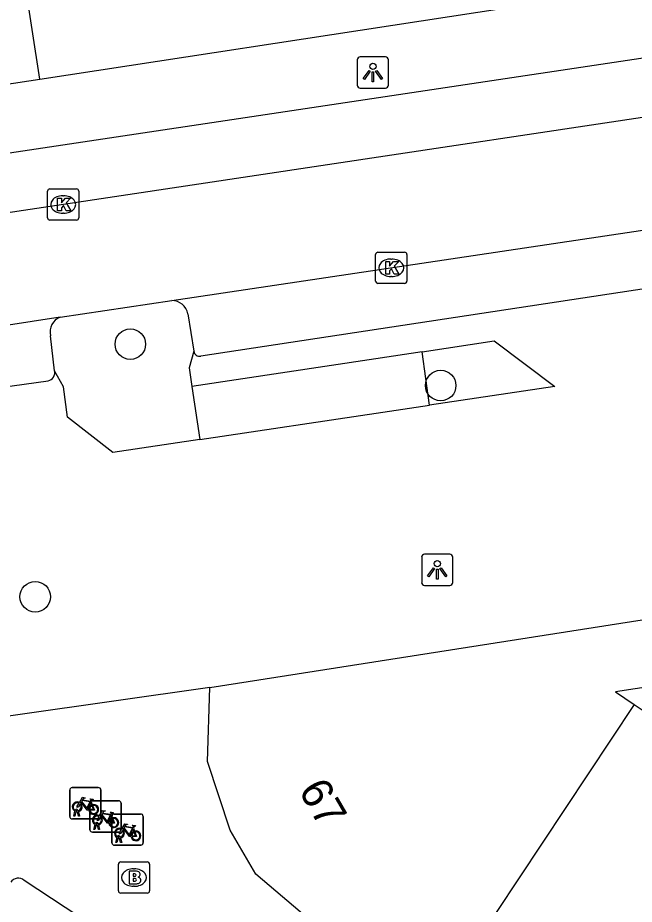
# Model space of a CAD drawing. Extents: x 159280 to 160375, y 384531 to 385872.
# Drawn here: x 159959.91 to 159979.67, y 384916.91 to 384945.31 of the extents above; entities that cross this region are included whole.
import ezdxf

# ---------------------------------------------------------------- set-up
doc = ezdxf.new("R2010")
doc.units = 0
for name, color, linetype in [('IMGEO_Boom', 7, 'Continuous'), ('IMGEO_Brandkraan', 7, 'Continuous'), ('IMGEO_Fietsenrek', 7, 'Continuous'), ('IMGEO_Haag', 7, 'Continuous'), ('IMGEO_Kolk', 7, 'Continuous'), ('IMGEO_Lichtpunt', 7, 'Continuous'), ('IMGEO_Pand', 7, 'Continuous'), ('IMGEO_Pand_nummerreeks', 7, 'Continuous'), ('IMGEO_Parkeervlak_open', 7, 'Continuous'), ('IMGEO_Rijbaan_lokaal_open', 7, 'Continuous'), ('IMGEO_Voetpad_open', 7, 'Continuous')]:
    doc.layers.add(name, color=color, linetype=linetype)

msp = doc.modelspace()

# ---------------------------------------------------------------- linework, layer by layer
at = {"layer": 'IMGEO_Boom'}
for centre in [(159963.522, 384934.849), (159973.467, 384933.524), (159960.474, 384926.758)]:
    msp.add_circle(centre, 0.489, dxfattribs=at)
at = {"layer": 'IMGEO_Brandkraan'}
for p, q in [((159963.213, 384918.262), (159964.065, 384918.262)), ((159963.138, 384917.336), (159963.138, 384918.188)), ((159963.626, 384918.042), (159963.651, 384918.042)), ((159964.139, 384918.188), (159964.139, 384917.336)), ((159963.649, 384917.482), (159963.624, 384917.482)), ((159964.065, 384917.262), (159963.213, 384917.262))]:
    msp.add_line(p, q, dxfattribs=at)
for points in [[(159963.213, 384918.262), (159964.065, 384918.262)], [(159963.138, 384917.336), (159963.138, 384918.188)], [(159964.139, 384918.188), (159964.139, 384917.336)], [(159963.486, 384917.962), (159963.486, 384917.562), (159963.699, 384917.562)], [(159963.717, 384917.962), (159963.486, 384917.962)], [(159963.665, 384917.881), (159963.611, 384917.881), (159963.611, 384917.805)], [(159963.611, 384917.805), (159963.664, 384917.805)], [(159963.673, 384917.729), (159963.611, 384917.729), (159963.611, 384917.648)], [(159963.611, 384917.648), (159963.673, 384917.648)], [(159964.065, 384917.262), (159963.213, 384917.262)]]:
    msp.add_lwpolyline(points, dxfattribs=at)
for centre, radius, start, end in [((159963.215, 384918.186), 0.0765, 91.552, 178.448), ((159963.215, 384918.186), 0.0765, 91.552, 178.448), ((159964.063, 384918.186), 0.0765, 1.552, 88.448), ((159964.063, 384918.186), 0.0765, 1.552, 88.448), ((159963.666, 384917.843), 0.0379, 267.8285, 90.9355), ((159963.674, 384917.688), 0.0404, 269.8759, 90.5077), ((159963.721, 384917.817), 0.145, 59.4692, 91.5367), ((159963.746, 384917.864), 0.0922, 285.5137, 58.1501), ((159963.751, 384917.672), 0.105, 301.3115, 78.989), ((159963.705, 384917.813), 0.251, 268.6676, 293.5347), ((159963.215, 384917.338), 0.0765, 181.552, 268.448), ((159963.215, 384917.338), 0.0765, 181.552, 268.448), ((159964.063, 384917.338), 0.0765, 271.552, 358.448), ((159964.063, 384917.338), 0.0765, 271.552, 358.448)]:
    msp.add_arc(centre, radius, start, end, dxfattribs=at)
for centre, major_axis, ratio, start_param, end_param in [((159963.625, 384917.762), (-0.387, 0.002), 0.722429, 4.712389, 7.853982), ((159963.65, 384917.762), (-0.39, 0.002), 0.717154, 1.570796, 4.712389)]:
    msp.add_ellipse(centre, major_axis=major_axis, ratio=ratio, start_param=start_param, end_param=end_param, dxfattribs=at)
at = {"layer": 'IMGEO_Fietsenrek'}
for p, q in [((159961.58, 384919.718), (159961.58, 384920.559)), ((159961.58, 384920.559), (159961.58, 384919.718)), ((159961.655, 384920.643), (159962.496, 384920.643)), ((159962.496, 384920.643), (159961.655, 384920.643)), ((159962.58, 384920.568), (159962.58, 384919.727)), ((159962.58, 384919.727), (159962.58, 384920.568)), ((159962.226, 384919.294), (159962.226, 384920.135)), ((159962.226, 384920.135), (159962.226, 384919.294)), ((159962.267, 384920.192), (159962.303, 384920.097)), ((159962.301, 384920.219), (159963.142, 384920.219)), ((159963.142, 384920.219), (159962.301, 384920.219)), ((159963.226, 384920.144), (159963.226, 384919.303)), ((159963.226, 384919.303), (159963.226, 384920.144)), ((159961.707, 384919.727), (159961.746, 384919.887)), ((159961.741, 384919.727), (159961.707, 384919.727)), ((159961.776, 384919.875), (159961.741, 384919.727)), ((159961.818, 384919.899), (159961.817, 384919.903)), ((159961.859, 384919.727), (159961.825, 384919.869)), ((159961.849, 384919.91), (159961.85, 384919.903)), ((159961.857, 384919.873), (159961.892, 384919.727)), ((159961.892, 384919.727), (159961.859, 384919.727)), ((159962.913, 384919.768), (159962.949, 384919.673)), ((159962.933, 384918.873), (159962.933, 384919.714)), ((159962.933, 384919.714), (159962.933, 384918.873)), ((159963.008, 384919.798), (159963.849, 384919.798)), ((159963.849, 384919.798), (159963.008, 384919.798)), ((159963.933, 384919.723), (159963.933, 384918.882)), ((159963.933, 384918.882), (159963.933, 384919.723)), ((159962.505, 384919.643), (159961.664, 384919.643)), ((159961.664, 384919.643), (159962.505, 384919.643)), ((159962.353, 384919.303), (159962.392, 384919.463)), ((159962.422, 384919.451), (159962.387, 384919.303)), ((159962.464, 384919.475), (159962.463, 384919.479)), ((159962.505, 384919.303), (159962.471, 384919.445)), ((159962.495, 384919.486), (159962.496, 384919.479)), ((159962.503, 384919.449), (159962.538, 384919.303)), ((159963.151, 384919.219), (159962.31, 384919.219)), ((159962.31, 384919.219), (159963.151, 384919.219)), ((159962.387, 384919.303), (159962.353, 384919.303)), ((159962.538, 384919.303), (159962.505, 384919.303)), ((159963.62, 384919.347), (159963.656, 384919.252)), ((159963.06, 384918.882), (159963.099, 384919.042)), ((159963.094, 384918.882), (159963.06, 384918.882)), ((159963.129, 384919.03), (159963.094, 384918.882)), ((159963.171, 384919.054), (159963.17, 384919.058)), ((159963.212, 384918.882), (159963.178, 384919.024)), ((159963.202, 384919.065), (159963.203, 384919.058)), ((159963.21, 384919.028), (159963.245, 384918.882)), ((159963.245, 384918.882), (159963.212, 384918.882)), ((159963.858, 384918.798), (159963.017, 384918.798)), ((159963.017, 384918.798), (159963.858, 384918.798))]:
    msp.add_line(p, q, dxfattribs=at)
for points in [[(159961.893, 384920.169), (159961.988, 384920.333), (159962.074, 384920.319), (159962.076, 384920.31), (159962.02, 384920.299), (159961.993, 384920.254), (159962.249, 384920.213)], [(159962.249, 384920.213), (159962.274, 384920.262), (159962.268, 384920.266), (159962.245, 384920.27), (159962.233, 384920.277), (159962.232, 384920.28), (159962.234, 384920.285), (159962.329, 384920.27), (159962.331, 384920.26), (159962.321, 384920.247), (159962.309, 384920.241), (159962.295, 384920.247), (159962.267, 384920.192)], [(159961.914, 384920.117), (159961.862, 384920.027), (159961.822, 384920.002), (159961.823, 384920.049), (159961.878, 384920.143)], [(159962.189, 384919.925), (159962.139, 384919.925), (159961.948, 384920.176), (159961.929, 384920.144)], [(159962.236, 384920.188), (159961.979, 384920.229), (159961.962, 384920.2), (159962.129, 384919.98), (159962.236, 384920.188)], [(159962.284, 384920.09), (159962.254, 384920.167), (159962.145, 384919.949), (159962.188, 384919.949)], [(159962.218, 384919.949), (159962.338, 384919.948), (159962.294, 384920.062)], [(159962.314, 384920.069), (159962.369, 384919.924), (159962.219, 384919.924)], [(159962.56, 384919.693), (159962.508, 384919.603), (159962.468, 384919.578), (159962.469, 384919.625), (159962.524, 384919.719)], [(159962.539, 384919.745), (159962.634, 384919.909), (159962.72, 384919.895), (159962.722, 384919.886), (159962.666, 384919.875), (159962.639, 384919.83), (159962.895, 384919.789)], [(159962.835, 384919.501), (159962.785, 384919.501), (159962.594, 384919.752), (159962.575, 384919.72)], [(159962.882, 384919.764), (159962.625, 384919.805), (159962.608, 384919.776), (159962.775, 384919.556), (159962.882, 384919.764)], [(159962.93, 384919.666), (159962.9, 384919.743), (159962.791, 384919.525), (159962.834, 384919.525)], [(159962.895, 384919.789), (159962.92, 384919.838), (159962.914, 384919.842), (159962.891, 384919.846), (159962.879, 384919.853), (159962.878, 384919.856), (159962.88, 384919.861), (159962.975, 384919.846), (159962.977, 384919.836), (159962.967, 384919.823), (159962.955, 384919.817), (159962.941, 384919.823), (159962.913, 384919.768)], [(159962.864, 384919.525), (159962.984, 384919.524), (159962.94, 384919.638)], [(159962.96, 384919.645), (159963.015, 384919.5), (159962.865, 384919.5)], [(159963.246, 384919.324), (159963.341, 384919.488), (159963.427, 384919.474), (159963.429, 384919.465), (159963.373, 384919.454), (159963.346, 384919.409), (159963.602, 384919.368)], [(159963.589, 384919.343), (159963.332, 384919.384), (159963.315, 384919.355), (159963.482, 384919.135), (159963.589, 384919.343)], [(159963.602, 384919.368), (159963.627, 384919.417), (159963.621, 384919.421), (159963.598, 384919.425), (159963.586, 384919.432), (159963.585, 384919.435), (159963.587, 384919.44), (159963.682, 384919.425), (159963.684, 384919.415), (159963.674, 384919.402), (159963.662, 384919.396), (159963.648, 384919.402), (159963.62, 384919.347)], [(159963.267, 384919.272), (159963.215, 384919.182), (159963.175, 384919.157), (159963.176, 384919.204), (159963.231, 384919.298)], [(159963.542, 384919.08), (159963.492, 384919.08), (159963.301, 384919.331), (159963.282, 384919.299)], [(159963.637, 384919.245), (159963.607, 384919.322), (159963.498, 384919.104), (159963.541, 384919.104)], [(159963.571, 384919.104), (159963.691, 384919.103), (159963.647, 384919.217)], [(159963.667, 384919.224), (159963.722, 384919.079), (159963.572, 384919.079)]]:
    msp.add_lwpolyline(points, dxfattribs=at)
for centre, radius, start, end in [((159961.658, 384920.565), 0.0779, 92.4484, 184.2845), ((159961.658, 384920.565), 0.0779, 92.4484, 184.2845), ((159962.502, 384920.565), 0.0779, 2.4484, 94.2845), ((159962.502, 384920.565), 0.0779, 2.4484, 94.2845), ((159961.82, 384920.028), 0.159, 62.6766, 242.1369), ((159961.82, 384920.028), 0.129, 63.3192, 238.903), ((159961.82, 384920.028), 0.129, 283.6043, 43.4302), ((159961.82, 384920.028), 0.159, 283.5766, 46.6042), ((159962.347, 384919.944), 0.159, 113.3408, 178.3217), ((159962.347, 384919.944), 0.159, 187.0065, 105.7708), ((159962.347, 384919.944), 0.129, 113.923, 177.9556), ((159962.347, 384919.944), 0.129, 188.6715, 104.5883), ((159962.304, 384920.141), 0.0779, 92.4484, 184.2845), ((159962.304, 384920.141), 0.0779, 92.4484, 184.2845), ((159963.148, 384920.141), 0.0779, 2.4484, 94.2845), ((159963.148, 384920.141), 0.0779, 2.4484, 94.2845), ((159961.658, 384919.721), 0.0779, 182.4484, 274.2845), ((159961.658, 384919.721), 0.0779, 182.4484, 274.2845), ((159961.8, 384919.899), 0.0499, 12.8025, 158.6934), ((159961.82, 384920.028), 0.159, 253.9967, 271.7867), ((159961.8, 384919.899), 0.0174, 12.8025, 163.4502), ((159961.82, 384920.028), 0.129, 253.415, 269.0204), ((159962.466, 384919.604), 0.159, 62.6766, 242.1369), ((159962.466, 384919.604), 0.129, 63.3192, 238.903), ((159962.466, 384919.604), 0.129, 283.6043, 43.4302), ((159962.466, 384919.604), 0.159, 283.5766, 46.6042), ((159962.502, 384919.721), 0.0779, 272.4484, 4.2845), ((159962.502, 384919.721), 0.0779, 272.4484, 4.2845), ((159962.993, 384919.52), 0.159, 187.0065, 105.7708), ((159963.011, 384919.72), 0.0779, 92.4484, 184.2845), ((159963.011, 384919.72), 0.0779, 92.4484, 184.2845), ((159963.855, 384919.72), 0.0779, 2.4484, 94.2845), ((159963.855, 384919.72), 0.0779, 2.4484, 94.2845), ((159962.446, 384919.475), 0.0499, 12.8025, 158.6934), ((159962.466, 384919.604), 0.159, 253.9967, 271.7867), ((159962.446, 384919.475), 0.0174, 12.8025, 163.4502), ((159962.466, 384919.604), 0.129, 253.415, 269.0204), ((159962.993, 384919.52), 0.159, 113.3408, 178.3217), ((159962.993, 384919.52), 0.129, 113.923, 177.9556), ((159962.993, 384919.52), 0.129, 188.6715, 104.5883), ((159962.304, 384919.297), 0.0779, 182.4484, 274.2845), ((159962.304, 384919.297), 0.0779, 182.4484, 274.2845), ((159963.173, 384919.183), 0.159, 62.6766, 242.1369), ((159963.173, 384919.183), 0.129, 63.3192, 238.903), ((159963.153, 384919.054), 0.0499, 12.8025, 158.6934), ((159963.148, 384919.297), 0.0779, 272.4484, 4.2845), ((159963.148, 384919.297), 0.0779, 272.4484, 4.2845), ((159963.173, 384919.183), 0.129, 283.6043, 43.4302), ((159963.173, 384919.183), 0.159, 283.5766, 46.6042), ((159963.7, 384919.099), 0.159, 113.3408, 178.3217), ((159963.7, 384919.099), 0.159, 187.0065, 105.7708), ((159963.7, 384919.099), 0.129, 113.923, 177.9556), ((159963.7, 384919.099), 0.129, 188.6715, 104.5883), ((159963.011, 384918.876), 0.0779, 182.4484, 274.2845), ((159963.011, 384918.876), 0.0779, 182.4484, 274.2845), ((159963.173, 384919.183), 0.159, 253.9967, 271.7867), ((159963.153, 384919.054), 0.0174, 12.8025, 163.4502), ((159963.173, 384919.183), 0.129, 253.415, 269.0204), ((159963.855, 384918.876), 0.0779, 272.4484, 4.2845), ((159963.855, 384918.876), 0.0779, 272.4484, 4.2845)]:
    msp.add_arc(centre, radius, start, end, dxfattribs=at)
at = {"layer": 'IMGEO_Haag'}
for points in [[(159973.107, 384932.892), (159972.877, 384934.605)], [(159965.496, 384933.493), (159965.753, 384931.796)]]:
    msp.add_lwpolyline(points, dxfattribs=at)
at = {"layer": 'IMGEO_Kolk'}
for p, q in [((159960.87, 384938.898), (159960.87, 384939.75)), ((159960.945, 384939.824), (159961.797, 384939.824)), ((159961.358, 384939.604), (159961.383, 384939.604)), ((159961.871, 384939.75), (159961.871, 384938.898)), ((159961.381, 384939.044), (159961.356, 384939.044)), ((159961.797, 384938.824), (159960.945, 384938.824)), ((159971.383, 384936.871), (159971.383, 384937.723)), ((159971.458, 384937.797), (159972.31, 384937.797)), ((159971.871, 384937.577), (159971.896, 384937.577)), ((159972.384, 384937.723), (159972.384, 384936.871)), ((159971.894, 384937.017), (159971.869, 384937.017)), ((159972.31, 384936.797), (159971.458, 384936.797))]:
    msp.add_line(p, q, dxfattribs=at)
for points in [[(159960.87, 384938.898), (159960.87, 384939.75)], [(159960.945, 384939.824), (159961.797, 384939.824)], [(159961.871, 384939.75), (159961.871, 384938.898)], [(159961.191, 384939.524), (159961.314, 384939.524), (159961.314, 384939.373), (159961.444, 384939.524), (159961.608, 384939.524), (159961.462, 384939.373), (159961.615, 384939.124), (159961.463, 384939.124), (159961.378, 384939.288), (159961.314, 384939.221), (159961.314, 384939.124), (159961.191, 384939.124), (159961.191, 384939.524)], [(159961.797, 384938.824), (159960.945, 384938.824)], [(159971.383, 384936.871), (159971.383, 384937.723)], [(159971.458, 384937.797), (159972.31, 384937.797)], [(159972.384, 384937.723), (159972.384, 384936.871)], [(159971.704, 384937.497), (159971.827, 384937.497), (159971.827, 384937.346), (159971.957, 384937.497), (159972.121, 384937.497), (159971.975, 384937.346), (159972.128, 384937.097), (159971.976, 384937.097), (159971.891, 384937.261), (159971.827, 384937.194), (159971.827, 384937.097), (159971.704, 384937.097), (159971.704, 384937.497)], [(159972.31, 384936.797), (159971.458, 384936.797)]]:
    msp.add_lwpolyline(points, dxfattribs=at)
for centre, start, end in [((159960.947, 384939.748), 91.552, 178.448), ((159960.947, 384939.748), 91.552, 178.448), ((159961.795, 384939.748), 1.552, 88.448), ((159961.795, 384939.748), 1.552, 88.448), ((159960.947, 384938.9), 181.552, 268.448), ((159960.947, 384938.9), 181.552, 268.448), ((159961.795, 384938.9), 271.552, 358.448), ((159961.795, 384938.9), 271.552, 358.448), ((159971.46, 384937.721), 91.552, 178.448), ((159971.46, 384937.721), 91.552, 178.448), ((159972.308, 384937.721), 1.552, 88.448), ((159972.308, 384937.721), 1.552, 88.448), ((159971.46, 384936.873), 181.552, 268.448), ((159971.46, 384936.873), 181.552, 268.448), ((159972.308, 384936.873), 271.552, 358.448), ((159972.308, 384936.873), 271.552, 358.448)]:
    msp.add_arc(centre, 0.0765, start, end, dxfattribs=at)
for centre, major_axis, ratio, start_param, end_param in [((159961.357, 384939.324), (-0.387, 0.002), 0.722429, 4.712389, 7.853982), ((159961.382, 384939.324), (-0.39, 0.002), 0.717154, 1.570796, 4.712389), ((159971.87, 384937.297), (-0.387, 0.002), 0.722429, 4.712389, 7.853982), ((159971.895, 384937.297), (-0.39, 0.002), 0.717154, 1.570796, 4.712389)]:
    msp.add_ellipse(centre, major_axis=major_axis, ratio=ratio, start_param=start_param, end_param=end_param, dxfattribs=at)
at = {"layer": 'IMGEO_Lichtpunt'}
for p, q in [((159970.796, 384943.955), (159970.796, 384943.148)), ((159970.796, 384943.955), (159970.796, 384943.148)), ((159971.698, 384944.05), (159970.89, 384944.05)), ((159971.698, 384944.05), (159970.89, 384944.05)), ((159971.792, 384943.148), (159971.792, 384943.955)), ((159971.792, 384943.148), (159971.792, 384943.955)), ((159970.89, 384943.054), (159971.698, 384943.054)), ((159970.89, 384943.054), (159971.698, 384943.054)), ((159972.858, 384928.023), (159972.858, 384927.216)), ((159972.858, 384928.023), (159972.858, 384927.216)), ((159973.76, 384928.118), (159972.952, 384928.118)), ((159973.76, 384928.118), (159972.952, 384928.118)), ((159973.854, 384927.216), (159973.854, 384928.023)), ((159973.854, 384927.216), (159973.854, 384928.023)), ((159972.952, 384927.122), (159973.76, 384927.122)), ((159972.952, 384927.122), (159973.76, 384927.122))]:
    msp.add_line(p, q, dxfattribs=at)
for points in [[(159971.17, 384943.619), (159971.209, 384943.591), (159971.021, 384943.329), (159970.983, 384943.356), (159971.17, 384943.619)], [(159971.272, 384943.571), (159971.319, 384943.571), (159971.319, 384943.249), (159971.272, 384943.249), (159971.272, 384943.571)], [(159971.382, 384943.591), (159971.42, 384943.618), (159971.607, 384943.356), (159971.568, 384943.328), (159971.382, 384943.591)], [(159973.232, 384927.687), (159973.271, 384927.659), (159973.083, 384927.397), (159973.045, 384927.424), (159973.232, 384927.687)], [(159973.334, 384927.639), (159973.381, 384927.639), (159973.381, 384927.317), (159973.334, 384927.317), (159973.334, 384927.639)], [(159973.444, 384927.659), (159973.482, 384927.686), (159973.669, 384927.424), (159973.63, 384927.396), (159973.444, 384927.659)]]:
    msp.add_lwpolyline(points, dxfattribs=at)
for centre in [(159971.295, 384943.753), (159973.357, 384927.821)]:
    msp.add_circle(centre, 0.0994, dxfattribs=at)
for centre, start, end in [((159970.89, 384943.955), 90, 180), ((159970.89, 384943.955), 90, 180), ((159971.698, 384943.955), 0, 90), ((159971.698, 384943.955), 0, 90), ((159970.89, 384943.148), 180, 270), ((159970.89, 384943.148), 180, 270), ((159971.698, 384943.148), 270, 0), ((159971.698, 384943.148), 270, 360), ((159972.952, 384928.023), 90, 180), ((159972.952, 384928.023), 90, 180), ((159973.76, 384928.023), 0, 90), ((159973.76, 384928.023), 0, 90), ((159972.952, 384927.216), 180, 270), ((159972.952, 384927.216), 180, 270), ((159973.76, 384927.216), 270, 0), ((159973.76, 384927.216), 270, 360)]:
    msp.add_arc(centre, 0.0946, start, end, dxfattribs=at)
at = {"layer": 'IMGEO_Pand'}
for points in [[(159966.07, 384923.849), (159984.158, 384926.682)], [(159984.158, 384926.682), (159984.522, 384924.544), (159979.066, 384923.712), (159979.666, 384923.309)], [(159973.774, 384914.418), (159971.772, 384915.74), (159971.487, 384915.309), (159969.395, 384916.303), (159967.542, 384917.867), (159966.719, 384919.284), (159965.995, 384921.481), (159966.07, 384923.849)], [(159979.666, 384923.309), (159973.774, 384914.418)], [(159979.666, 384923.309), (159982.004, 384921.742), (159980.558, 384919.553), (159982.477, 384918.284)]]:
    msp.add_lwpolyline(points, dxfattribs=at)
at = {"layer": 'IMGEO_Parkeervlak_open'}
for points in [[(159965.368, 384935.821), (159965.558, 384934.629)], [(159961.091, 384934), (159960.966, 384935.121)]]:
    msp.add_lwpolyline(points, dxfattribs=at)
for centre, radius, start, end in [((159964.854, 384935.723), 0.523, 10.837, 90.6442), ((159961.474, 384935.238), 0.522, 112.8117, 192.9902)]:
    msp.add_arc(centre, radius, start, end, dxfattribs=at)
at = {"layer": 'IMGEO_Rijbaan_lokaal_open'}
for points in [[(159991.306, 384943.822), (159958.878, 384938.949)], [(159964.848, 384936.246), (159980.373, 384938.566)], [(159961.272, 384935.719), (159964.848, 384936.246)], [(159961.272, 384935.719), (159954.563, 384934.683)]]:
    msp.add_lwpolyline(points, dxfattribs=at)
at = {"layer": 'IMGEO_Voetpad_open'}
for points in [[(159959.209, 384940.91), (160040.921, 384953.179)], [(159960.619, 384943.336), (160000, 384949.373), (160022.714, 384952.82)], [(159960.619, 384943.336), (159960.15, 384946.398)], [(159958.571, 384943.024), (159960.619, 384943.336)], [(159980.232, 384936.834), (159980.06, 384936.63), (159965.782, 384934.464)], [(159972.877, 384934.605), (159975.185, 384934.952), (159977.123, 384933.49), (159973.107, 384932.892)], [(159965.558, 384934.629), (159965.406, 384934.087), (159965.496, 384933.493)], [(159972.877, 384934.605), (159971.384, 384934.38), (159965.496, 384933.493)], [(159965.753, 384931.796), (159962.964, 384931.38), (159961.505, 384932.507), (159961.378, 384933.479), (159961.091, 384934)], [(159955.425, 384932.916), (159960.891, 384933.677)], [(159965.753, 384931.796), (159971.614, 384932.669), (159973.107, 384932.892)], [(159966.07, 384923.849), (159950.751, 384921.669)], [(160017.484, 384877.679), (160017.389, 384877.749), (160017.267, 384877.853), (160017.156, 384877.969), (160017.055, 384878.093), (160016.965, 384878.227), (160016.888, 384878.367), (160016.823, 384878.515), (160016.772, 384878.667), (160016.735, 384878.823), (160016.712, 384878.982), (160016.628, 384879.955), (160016.593, 384880.076), (160016.548, 384880.193), (160016.493, 384880.306), (160016.427, 384880.414), (160016.353, 384880.515), (160016.269, 384880.609), (160016.232, 384880.646), (160000, 384891.362), (159975.638, 384907.458), (159970.364, 384910.928), (159967.975, 384912.5), (159960.117, 384917.67)]]:
    msp.add_lwpolyline(points, dxfattribs=at)
for centre, radius, start, end in [((159965.745, 384934.648), 0.187, 185.7169, 281.5318), ((159960.844, 384933.93), 0.257, 280.628, 15.8408), ((159959.928, 384917.457), 0.285, 48.5056, 146.4722)]:
    msp.add_arc(centre, radius, start, end, dxfattribs=at)

# ---------------------------------------------------------------- texts
at = {"layer": 'IMGEO_Pand_nummerreeks'}
msp.add_text('67', height=1, rotation=300.1482, dxfattribs=at).set_placement((159968.894, 384920.556))

doc.saveas('drawing.dxf')
